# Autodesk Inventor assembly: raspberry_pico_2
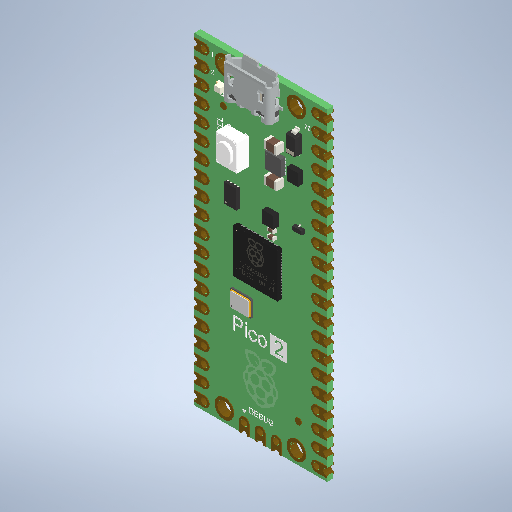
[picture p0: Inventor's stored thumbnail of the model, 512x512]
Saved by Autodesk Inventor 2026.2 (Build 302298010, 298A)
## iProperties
Created: 2026-06
Part Number: raspberry_pico_2
Description: FreeCAD Model
Document SubType Name: Assembly
Designer: mel
Authority: Unknown
Sending System: FreeCAD
Preprocessor: Open CASCADE STEP processor 7.8
Title: Open CASCADE Shape Model
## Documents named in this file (10)
- D:\travail\année 2026-2027\1 sti2d IT\poubelle à verre\raspberry-pico-2-microcontroller-rp2350-1.snapshot.5\raspberry_pico_2\raspberry_pico_2\raspberry_pico_2.iam
- D:\travail\année 2026-2027\1 sti2d IT\poubelle à verre\raspberry-pico-2-microcontroller-rp2350-1.snapshot.5\raspberry_pico_2\raspberry_pico_2\Groupe_pcb.iam
- D:\travail\année 2026-2027\1 sti2d IT\poubelle à verre\raspberry-pico-2-microcontroller-rp2350-1.snapshot.5\raspberry_pico_2\raspberry_pico_2\micro_usb_connector v17 v1.iam
- D:\travail\année 2026-2027\1 sti2d IT\poubelle à verre\raspberry-pico-2-microcontroller-rp2350-1.snapshot.5\raspberry_pico_2\raspberry_pico_2\LFXTAL055299Reel008.iam
- D:\travail\année 2026-2027\1 sti2d IT\poubelle à verre\raspberry-pico-2-microcontroller-rp2350-1.snapshot.5\raspberry_pico_2\raspberry_pico_2\tactile_switch.ipt
- D:\travail\année 2026-2027\1 sti2d IT\poubelle à verre\raspberry-pico-2-microcontroller-rp2350-1.snapshot.5\raspberry_pico_2\raspberry_pico_2\silkscreen_recto.iam
- D:\travail\année 2026-2027\1 sti2d IT\poubelle à verre\raspberry-pico-2-microcontroller-rp2350-1.snapshot.5\raspberry_pico_2\raspberry_pico_2\Components_recto.iam
- D:\travail\année 2026-2027\1 sti2d IT\poubelle à verre\raspberry-pico-2-microcontroller-rp2350-1.snapshot.5\raspberry_pico_2\raspberry_pico_2\TP_verso.iam
- D:\travail\année 2026-2027\1 sti2d IT\poubelle à verre\raspberry-pico-2-microcontroller-rp2350-1.snapshot.5\raspberry_pico_2\raspberry_pico_2\Silkscreen_bottom-p1.iam
- D:\travail\année 2026-2027\1 sti2d IT\poubelle à verre\raspberry-pico-2-microcontroller-rp2350-1.snapshot.5\raspberry_pico_2\raspberry_pico_2\Silkscreen_bottom_p2.iam
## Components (9 placed, 9 different names)
1. 2632 [sub-assembly]
2. 2641 [sub-assembly]
3. 2650 [sub-assembly]
4. 2651
5. 2663 [sub-assembly]
6. 2782 [sub-assembly]
7. 2790 [sub-assembly]
8. 2813 [sub-assembly]
9. 2845 [sub-assembly]
